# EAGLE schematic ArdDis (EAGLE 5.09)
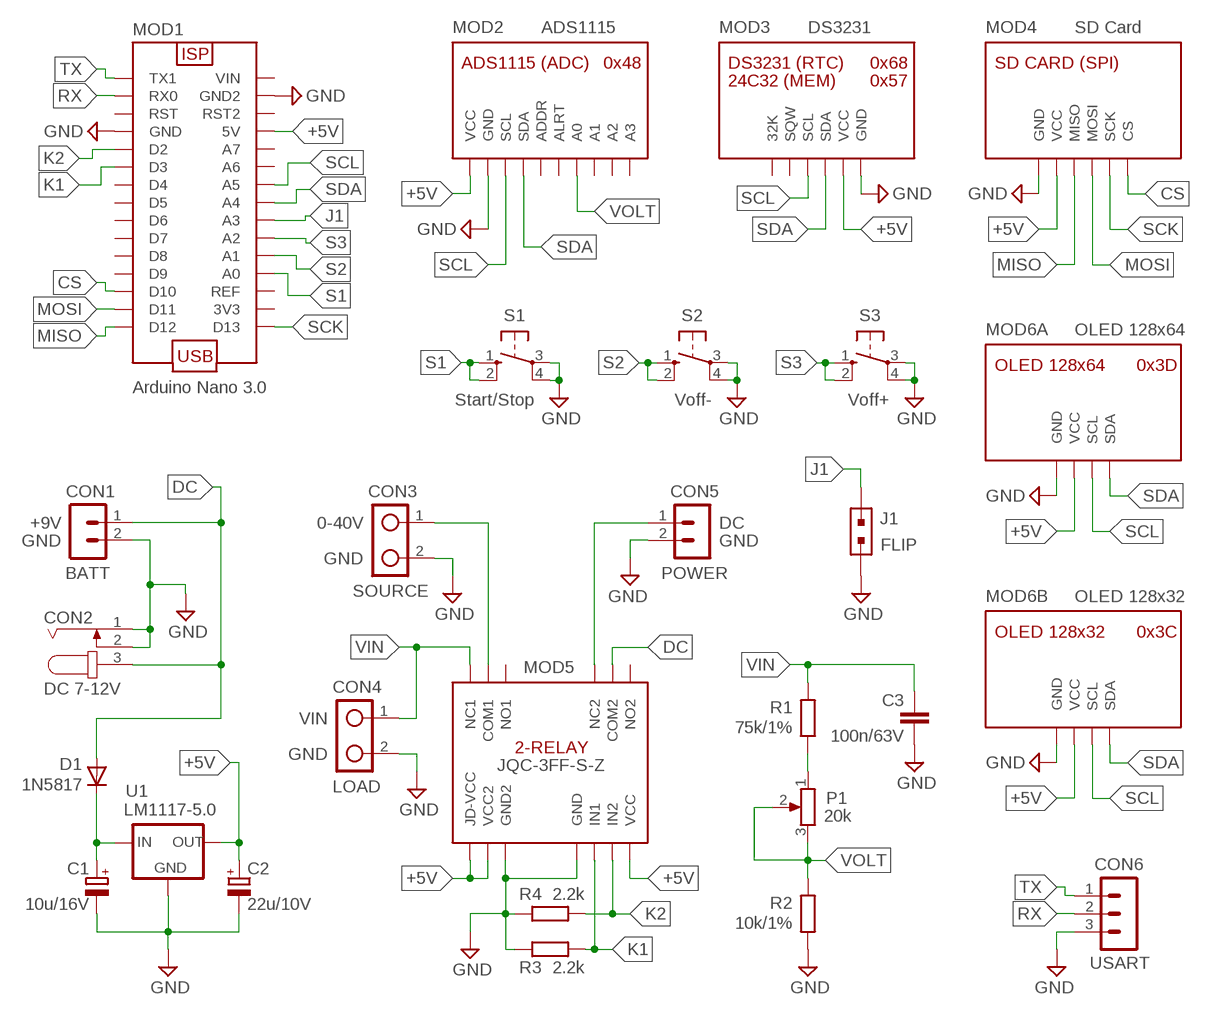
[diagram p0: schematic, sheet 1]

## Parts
C1  10u/16V  C5/2.5  [C5/2.5]
C2  22u/10V  C5/2.5  [C5/2.5]
C3  100n/63V  C5-025X075  [C5-025X075]
CON1  BATT  CON-2PIN  [CON-2PIN]
CON2  DC 7-12V  DC-JACK  [DC-JACK]
CON3  SOURCE  CON-ARK2  [CON-ARK2]
CON4  LOAD  CON-ARK2  [CON-ARK2]
CON5  POWER  CON-2PIN  [CON-2PIN]
CON6  USART  CON-3X1  [CON-3X1]
D1  1N5817  PAD-D7.5N  [D-7.5]
J1  FLIP  J-2X1_2  [J-2X1]
MOD1  Arduino Nano 3.0  MOD-ARDUINO_NANO  [MOD-ARDUINO_NANO]
MOD2  ADS1115  MOD-ADS1115  [MOD-ADS1115]
MOD3  DS3231  MOD-DS3231  [MOD-DS3231]
MOD4  SD Card  MOD-SD_CARD  [MOD-SD_CARD]
MOD5  JQC-3FF-S-Z  MOD-RELAY_2X  [MOD-RELAY_2X]
MOD6A  OLED 128x64  MOD-OLED128X64  [MOD-OLED128X64]
MOD6B  OLED 128x32  MOD-OLED128X32  [MOD-OLED128X32]
P1  20k  P-HELITRIM  [P-HV]
R1  75k/1%  R10R7  [R7]
R2  10k/1%  R10R7  [R7]
R3  2.2k  R10R7  [R7]
R4  2.2k  R10R7  [R7]
S1  Start/Stop  10-XX  [B3F-10XX]
S2  Voff-  10-XX  [B3F-10XX]
S3  Voff+  10-XX  [B3F-10XX]
U1  LM1117-5.0  LM1117-FIX  [SOT223]

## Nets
+5V: C2.+ MOD1.5V MOD2.VCC MOD3.VCC MOD4.VCC MOD5.JD-VCC MOD5.VCC MOD5.VCC2 MOD6A.VCC MOD6B.VCC U1.2(OUT)
CS: MOD1.D10 MOD4.CS
DC: CON1.1 CON2.3 D1.A MOD5.COM2
GND: C1.- C2.- C3.2 CON1.2 CON2.1 CON2.2 CON3.2 CON4.2 CON5.2 CON6.3 J1.2 MOD1.GND MOD1.GND2 MOD2.GND MOD3.GND MOD4.GND MOD5.GND MOD5.GND2 MOD6A.GND MOD6B.GND R2.1 R3.1 R4.1 S1.3(P) S1.4(P1) S2.3(P) S2.4(P1) S3.3(P) S3.4(P1) U1.1(GND)
J1: J1.1 MOD1.A3
K1: MOD1.D3 MOD5.IN1 R3.2
K2: MOD1.D2 MOD5.IN2 R4.2
MISO: MOD1.D12 MOD4.MISO
MOSI: MOD1.D11 MOD4.MOSI
N$1: C1.+ D1.C U1.3(IN)
N$2: P1.1 R1.1
N$3: CON3.1 MOD5.COM1
N$4: CON5.1 MOD5.NC2
RX: CON6.2 MOD1.RX0
S1: MOD1.A0 S1.1(S) S1.2(S1)
S2: MOD1.A1 S2.1(S) S2.2(S1)
S3: MOD1.A2 S3.1(S) S3.2(S1)
SCK: MOD1.D13 MOD4.SCK
SCL: MOD1.A5 MOD2.SCL MOD3.SCL MOD6A.SCL MOD6B.SCL
SDA: MOD1.A4 MOD2.SDA MOD3.SDA MOD6A.SDA MOD6B.SDA
TX: CON6.1 MOD1.TX1
VIN: C3.1 CON4.1 MOD5.NC1 R1.2
VOLT: MOD2.A0 P1.2 P1.3 R2.2
Unconnected: MOD1.A6 MOD1.A7 MOD1.D4 MOD1.D5 MOD1.D6 MOD1.D7 MOD1.D8 MOD1.D9 MOD1.RST MOD1.RST2 MOD2.A1 MOD2.A2 MOD2.A3 MOD2.ADDR MOD2.ALRT MOD3.32K MOD3.SQW MOD5.NO1 MOD5.NO2

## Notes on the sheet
- +9V | 0-40V | DC
- GND | GND
- GND
- VIN
- GND

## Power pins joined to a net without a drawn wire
3V3: MOD1.3V3
REF: MOD1.REF
VIN: MOD1.VIN

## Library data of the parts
C1 C2 = _my:C5/2.5
C3 = _my:C5-025X075
CON1 CON5 = _my:CON-2PIN
CON2 = _my:DC-JACK
CON3 CON4 = _my:CON-ARK2
CON6 = _my:CON-3X1
D1 = _my:PAD-D7.5
J1 = _my:J-2X1_2
MOD1 = _my:MOD-ARDUINO_NANO
MOD2 = _my:MOD-ADS1115
MOD3 = _my:MOD-DS3231
MOD4 = _my:MOD-SD_CARD
MOD5 = _my:MOD-RELAY_2X
MOD6A = _my:MOD-OLED128X64
MOD6B = _my:MOD-OLED128X32
P1 = _my:P-HELITRIM
R1-R4 = _my:R10
S1-S3 = switch-omron:10-XX: OMRON SWITCH
U1 = _my:LM1117-FIX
